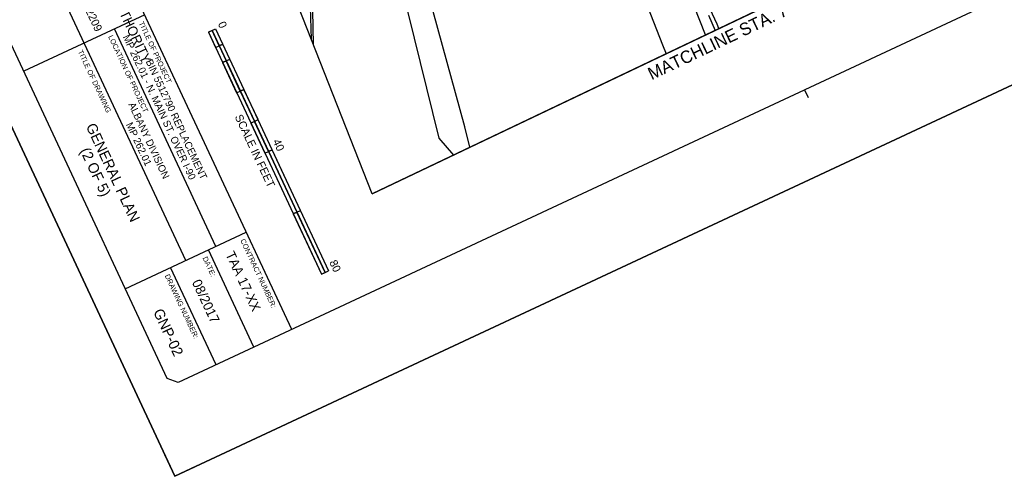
# Model space of a CAD drawing. Extents: x 1040364 to 1041050, y 1127298 to 1128100.
# Drawn here: x 1040605.1 to 1040900.2, y 1127297.6 to 1127434.3 of the extents above; entities that cross this region are included whole.
import ezdxf

# ---------------------------------------------------------------- set-up
doc = ezdxf.new("R2010")
doc.units = 0
for name, color, linetype in [('clip boundary', 7, 'Continuous'), ('LAWA', 7, 'Continuous'), ('LELB', 7, 'Continuous'), ('LFILL_P', 7, 'Continuous'), ('NML_P', 7, 'Continuous'), ('NML_P_T', 7, 'Continuous'), ('NSB_P', 7, 'Continuous'), ('O_Details_Text Title and Subtitle Proposed_P_T', 7, 'Continuous'), ('SHEET_BORDER', 7, 'Continuous'), ('SHEET_BORDER_CUT', 7, 'Continuous'), ('SHEET_BORDER_TEXT', 7, 'Continuous')]:
    doc.layers.add(name, color=color, linetype=linetype)

msp = doc.modelspace()

# ---------------------------------------------------------------- linework, layer by layer
at = {"layer": 'clip boundary'}
for points in [[(1040762.51, 1128099.9), (1041050.31, 1127483.8), (1040651.66, 1127297.58), (1040363.86, 1127913.67)], [(1040504.79, 1127904.67), (1040760.34, 1127999.71), (1040984.84, 1127512.73), (1040710.81, 1127382.18)]]:
    msp.add_lwpolyline(points, close=True, dxfattribs=at)
at = {"layer": 'LAWA'}
for points in [[(1040692.56, 1127428.47), (1040690.16, 1127505.27), (1040685.49, 1127527.45), (1040638.23, 1127566.26)], [(1040755.88, 1127521.48), (1040742.57, 1127509.97), (1040731.76, 1127475.8), (1040721.5, 1127436.46), (1040730.8, 1127398.83), (1040735.21, 1127393.81)]]:
    msp.add_lwpolyline(points, dxfattribs=at)
at = {"layer": 'LELB'}
for points in [[(1040810.73, 1127429.78), (1040803.7, 1127447.62), (1040790.28, 1127475.04), (1040767.31, 1127518.61), (1040755.95, 1127542.69), (1040738.89, 1127579.03), (1040723.86, 1127612.81), (1040706.92, 1127651.68), (1040695, 1127676.62), (1040683.43, 1127703.39), (1040670.93, 1127728.26), (1040660.81, 1127750.01), (1040651.71, 1127772.02), (1040637.02, 1127804.07), (1040629.69, 1127830.98), (1040616.26, 1127871.74), (1040612.35, 1127873.83), (1040609.66, 1127871.77), (1040608.53, 1127867.34), (1040606.04, 1127852.48)], [(1040814.73, 1127431.69), (1040814.14, 1127433.03), (1040793.33, 1127477.77), (1040771.38, 1127522.24)], [(1040759.32, 1127519.12), (1040779.14, 1127474.66), (1040797.84, 1127426.8), (1040798.87, 1127424.14)], [(1040693.16, 1127426.93), (1040692.18, 1127477.93)], [(1040740.09, 1127396.13), (1040738.57, 1127402.26), (1040722.39, 1127461.23)]]:
    msp.add_lwpolyline(points, dxfattribs=at)
at = {"layer": 'LFILL_P'}
msp.add_lwpolyline([(1040811.57, 1127435.71), (1040813.59, 1127431.15)], dxfattribs=at)
at = {"layer": 'NML_P'}
msp.add_line((1040710.81, 1127382.18), (1040984.84, 1127512.73), dxfattribs=at)
at = {"layer": 'NSB_P'}
for p, q in [((1040661.7, 1127430.57), (1040663.88, 1127431.58)), ((1040662.79, 1127431.07), (1040661.7, 1127430.57)), ((1040661.7, 1127430.57), (1040695.56, 1127358.08)), ((1040661.7, 1127430.57), (1040663.82, 1127426.04)), ((1040662.79, 1127431.07), (1040696.65, 1127358.59)), ((1040664.91, 1127426.54), (1040662.79, 1127431.07)), ((1040663.88, 1127431.58), (1040697.74, 1127359.1)), ((1040663.82, 1127426.04), (1040665.99, 1127427.05)), ((1040663.82, 1127426.04), (1040664.91, 1127426.54)), ((1040665.99, 1127427.05), (1040664.91, 1127426.54)), ((1040664.91, 1127426.54), (1040667.02, 1127422.01)), ((1040668.11, 1127422.52), (1040665.99, 1127427.05)), ((1040665.94, 1127421.5), (1040668.11, 1127422.52)), ((1040667.02, 1127422.01), (1040665.94, 1127421.5)), ((1040665.94, 1127421.5), (1040670.17, 1127412.44)), ((1040667.02, 1127422.01), (1040668.11, 1127422.52)), ((1040671.25, 1127412.95), (1040667.02, 1127422.01)), ((1040670.17, 1127412.44), (1040672.34, 1127413.46)), ((1040670.17, 1127412.44), (1040671.25, 1127412.95)), ((1040672.34, 1127413.46), (1040671.25, 1127412.95)), ((1040671.25, 1127412.95), (1040675.49, 1127403.89)), ((1040676.57, 1127404.4), (1040672.34, 1127413.46)), ((1040674.4, 1127403.38), (1040676.57, 1127404.4)), ((1040675.49, 1127403.89), (1040674.4, 1127403.38)), ((1040674.4, 1127403.38), (1040678.63, 1127394.32)), ((1040675.49, 1127403.89), (1040676.57, 1127404.4)), ((1040679.72, 1127394.83), (1040675.49, 1127403.89)), ((1040678.63, 1127394.32), (1040680.81, 1127395.34)), ((1040678.63, 1127394.32), (1040679.72, 1127394.83)), ((1040680.81, 1127395.34), (1040679.72, 1127394.83)), ((1040679.72, 1127394.83), (1040688.18, 1127376.71)), ((1040689.27, 1127377.22), (1040680.81, 1127395.34)), ((1040687.1, 1127376.2), (1040689.27, 1127377.22)), ((1040688.18, 1127376.71), (1040687.1, 1127376.2)), ((1040687.1, 1127376.2), (1040695.56, 1127358.08)), ((1040688.18, 1127376.71), (1040689.27, 1127377.22)), ((1040696.65, 1127358.59), (1040688.18, 1127376.71)), ((1040695.56, 1127358.08), (1040697.74, 1127359.1)), ((1040695.56, 1127358.08), (1040696.65, 1127358.59))]:
    msp.add_line(p, q, dxfattribs=at)
at = {"layer": 'SHEET_BORDER'}
for p, q in [((1040686.67, 1127341.52), (1040544.54, 1127645.78)), ((1040654.92, 1127362.22), (1040594.08, 1127492.46)), ((1040642.62, 1127435.81), (1040606.38, 1127418.88)), ((1040663.98, 1127366.45), (1040633.56, 1127431.57)), ((1040840.41, 1127413.34), (1040841.46, 1127411.08)), ((1040636.8, 1127353.76), (1040673.04, 1127370.69)), ((1040675.34, 1127336.23), (1040661.72, 1127365.4)), ((1040664.01, 1127330.94), (1040650.39, 1127360.11))]:
    msp.add_line(p, q, dxfattribs=at)
msp.add_lwpolyline([(1040652.69, 1127325.65), (1040649.37, 1127326.86), (1040384.85, 1127893.12), (1040386.05, 1127896.45), (1040761.49, 1128071.82), (1040764.81, 1128070.62), (1041029.33, 1127504.35), (1041028.12, 1127501.03)], close=True, dxfattribs=at)
at = {"layer": 'SHEET_BORDER_CUT'}
msp.add_lwpolyline([(1040363.86, 1127913.67), (1040651.66, 1127297.58), (1041050.31, 1127483.8), (1040762.51, 1128099.9)], close=True, dxfattribs=at)
msp.add_lwpolyline([(1040658.07, 1127300.57), (1040651.66, 1127297.58), (1040648.67, 1127303.99)], dxfattribs=at)
at = {"layer": 'SHEET_BORDER_TEXT'}
msp.add_line((1040651.66, 1127297.58), (1040651.66, 1127297.58), dxfattribs=at)

# ---------------------------------------------------------------- texts
at = {"layer": 'NML_P_T'}
msp.add_text('MATCHLINE STA. 7+50 - SEE DWG. GNP-03', height=3.744, rotation=25.4736, dxfattribs=at).set_placement((1040794.55, 1127416.18))
at = {"layer": 'NSB_P'}
for s, p in [('0', (1040664.48, 1127433.12)), ('SCALE IN FEET', (1040669.54, 1127405.28)), ('40', (1040680.93, 1127397.92)), ('80', (1040697.86, 1127361.68))]:
    msp.add_text(s, height=2.4, rotation=295.0387, dxfattribs=at).set_placement(p)
at = {"layer": 'O_Details_Text Title and Subtitle Proposed_P_T'}
for s, height, p in [('GENERAL PLAN', 3.1248, (1040624.92, 1127402.43)), ('(2 OF 5)', 3.125, (1040623.16, 1127395.13)), ('GNP-02', 3.125, (1040645.09, 1127346.86))]:
    msp.add_text(s, height=height, rotation=295.0387, dxfattribs=at).set_placement(p)
at = {"layer": 'SHEET_BORDER'}
for s, height, p in [('200 SOUTHERN BLVD., ALBANY, N.Y. 12209', 2.4, (1040599.61, 1127490.98)), ('NEW YORK STATE THRUWAY AUTHORITY', 2.88, (1040608.96, 1127491.97)), ('TITLE OF PROJECT', 1.5625, (1040640.79, 1127433.36)), ('LOCATION OF PROJECT', 1.5625, (1040631.62, 1127429.27)), ('TITLE OF DRAWING', 1.5625, (1040622.53, 1127424.83)), ('CONTRACT NUMBER:', 1.5625, (1040671.21, 1127368.24)), ('DATE:', 1.562, (1040659.89, 1127362.95)), ('DRAWING NUMBER:', 1.5625, (1040648.56, 1127357.66))]:
    msp.add_text(s, height=height, rotation=295.0387, dxfattribs=at).set_placement(p)
at = {"layer": 'SHEET_BORDER_TEXT'}
for s, height, p in [('MP 262.01 - N. MAIN ST. OVER I-90', 2.16, (1040635.98, 1127429.2)), ('BIN 5512790 REPLACEMENT', 2.16, (1040642.85, 1127421.85)), ('ALBANY DIVISION', 2.16, (1040637.65, 1127408.97)), ('MP 262.01', 2.16, (1040636.94, 1127402.97)), ('TAA 17-XX', 2.88, (1040666.76, 1127364.11)), ('08/2017', 2.88, (1040656.69, 1127355.7))]:
    msp.add_text(s, height=height, rotation=295.0387, dxfattribs=at).set_placement(p)

doc.saveas('drawing.dxf')
